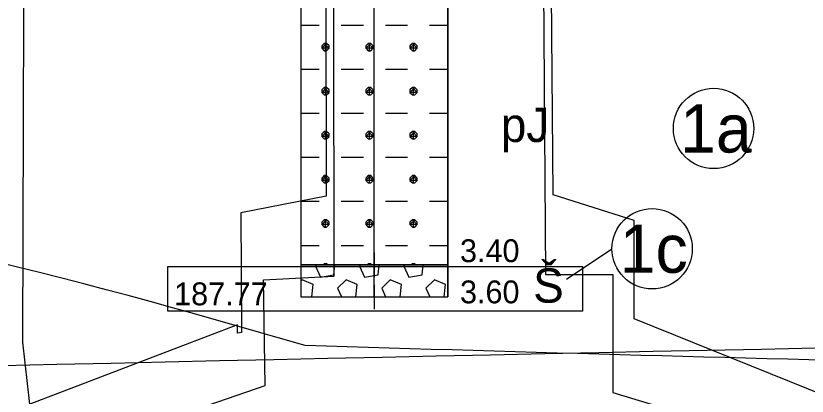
# Model space of a CAD drawing. Extents: x 3042 to 4120, y 576 to 2694.
# Drawn here: x 3366.29 to 3390.9, y 1724.37 to 1736.2 of the extents above; entities that cross this region are included whole.
import ezdxf

# ---------------------------------------------------------------- set-up
doc = ezdxf.new("R2010")
doc.units = 0
for name, color, linetype in [('17', 7, 'Continuous'), ('18', 7, 'Continuous'), ('51', 7, 'Continuous'), ('52', 7, 'Continuous'), ('53', 7, 'Continuous'), ('56', 7, 'Continuous'), ('HPV', 7, 'Continuous'), ('nádrže', 7, 'Continuous'), ('rozhraní', 7, 'Continuous')]:
    doc.layers.add(name, color=color, linetype=linetype)

msp = doc.modelspace()

# ---------------------------------------------------------------- linework, layer by layer
at = {"layer": '18'}
for p, q in [((3377.432, 1727.455), (3377.432, 1745.455)), ((3377.432, 1727.836), (3377.432, 1727.074)), ((3377.051, 1727.455), (3377.813, 1727.455))]:
    msp.add_line(p, q, dxfattribs=at)
at = {"layer": '51'}
for p, q in [((3375.146, 1735.917), (3375.722, 1735.917)), ((3376.408, 1735.917), (3377.094, 1735.917)), ((3377.779, 1735.917), (3378.465, 1735.917)), ((3379.151, 1735.917), (3379.718, 1735.917)), ((3375.912, 1735.117), (3375.912, 1735.346)), ((3377.284, 1735.117), (3377.284, 1735.346)), ((3378.656, 1735.117), (3378.656, 1735.346)), ((3375.146, 1734.546), (3375.722, 1734.546)), ((3376.408, 1734.546), (3377.094, 1734.546)), ((3377.779, 1734.546), (3378.465, 1734.546)), ((3379.151, 1734.546), (3379.718, 1734.546)), ((3375.912, 1733.746), (3375.912, 1733.974)), ((3377.284, 1733.746), (3377.284, 1733.974)), ((3378.656, 1733.746), (3378.656, 1733.974)), ((3375.146, 1733.174), (3375.722, 1733.174)), ((3376.408, 1733.174), (3377.094, 1733.174)), ((3377.779, 1733.174), (3378.465, 1733.174)), ((3379.151, 1733.174), (3379.718, 1733.174)), ((3375.912, 1732.374), (3375.912, 1732.603)), ((3377.284, 1732.374), (3377.284, 1732.603)), ((3378.656, 1732.374), (3378.656, 1732.603)), ((3375.146, 1731.803), (3375.722, 1731.803)), ((3376.408, 1731.803), (3377.094, 1731.803)), ((3377.779, 1731.803), (3378.465, 1731.803)), ((3379.151, 1731.803), (3379.718, 1731.803)), ((3375.912, 1731.003), (3375.912, 1731.231)), ((3377.284, 1731.003), (3377.284, 1731.231)), ((3378.656, 1731.003), (3378.656, 1731.231)), ((3375.146, 1730.431), (3375.722, 1730.431)), ((3376.408, 1730.431), (3377.094, 1730.431)), ((3377.779, 1730.431), (3378.465, 1730.431)), ((3379.151, 1730.431), (3379.718, 1730.431)), ((3375.912, 1729.631), (3375.912, 1729.86)), ((3377.284, 1729.631), (3377.284, 1729.86)), ((3378.656, 1729.631), (3378.656, 1729.86)), ((3375.146, 1729.059), (3375.722, 1729.059)), ((3376.408, 1729.059), (3377.094, 1729.059)), ((3377.779, 1729.059), (3378.465, 1729.059)), ((3379.151, 1729.059), (3379.718, 1729.059)), ((3375.651, 1728.455), (3375.608, 1728.412)), ((3375.874, 1728.488), (3375.841, 1728.455)), ((3375.912, 1728.455), (3375.912, 1728.488)), ((3375.917, 1728.455), (3375.951, 1728.488)), ((3377.022, 1728.455), (3376.979, 1728.412)), ((3377.246, 1728.488), (3377.213, 1728.455)), ((3377.284, 1728.455), (3377.284, 1728.488)), ((3377.289, 1728.455), (3377.322, 1728.488)), ((3378.394, 1728.455), (3378.351, 1728.412)), ((3378.618, 1728.488), (3378.584, 1728.455)), ((3378.656, 1728.455), (3378.656, 1728.488)), ((3378.66, 1728.455), (3378.694, 1728.488)), ((3376.293, 1727.726), (3376.414, 1727.455)), ((3377.665, 1727.726), (3377.786, 1727.455)), ((3379.037, 1727.726), (3379.157, 1727.455))]:
    msp.add_line(p, q, dxfattribs=at)
for points in [[(3375.146, 1728.455), (3379.718, 1728.455), (3379.718, 1737.455), (3375.146, 1737.455)], [(3375.146, 1727.455), (3379.718, 1727.455), (3379.718, 1728.455), (3375.146, 1728.455)]]:
    msp.add_lwpolyline(points, close=True, dxfattribs=at)
for points in [[(3375.874, 1735.346), (3375.798, 1735.27), (3375.798, 1735.194), (3375.874, 1735.117), (3375.951, 1735.117), (3376.027, 1735.194), (3376.027, 1735.27), (3375.951, 1735.346), (3375.874, 1735.346), (3376.027, 1735.194), (3375.798, 1735.194), (3375.951, 1735.346)], [(3377.246, 1735.346), (3377.17, 1735.27), (3377.17, 1735.194), (3377.246, 1735.117), (3377.322, 1735.117), (3377.398, 1735.194), (3377.398, 1735.27), (3377.322, 1735.346), (3377.246, 1735.346), (3377.398, 1735.194), (3377.17, 1735.194), (3377.322, 1735.346)], [(3378.618, 1735.346), (3378.541, 1735.27), (3378.541, 1735.194), (3378.618, 1735.117), (3378.694, 1735.117), (3378.77, 1735.194), (3378.77, 1735.27), (3378.694, 1735.346), (3378.618, 1735.346), (3378.77, 1735.194), (3378.541, 1735.194), (3378.694, 1735.346)], [(3375.874, 1733.974), (3375.798, 1733.898), (3375.798, 1733.822), (3375.874, 1733.746), (3375.951, 1733.746), (3376.027, 1733.822), (3376.027, 1733.898), (3375.951, 1733.974), (3375.874, 1733.974), (3376.027, 1733.822), (3375.798, 1733.822), (3375.951, 1733.974)], [(3377.246, 1733.974), (3377.17, 1733.898), (3377.17, 1733.822), (3377.246, 1733.746), (3377.322, 1733.746), (3377.398, 1733.822), (3377.398, 1733.898), (3377.322, 1733.974), (3377.246, 1733.974), (3377.398, 1733.822), (3377.17, 1733.822), (3377.322, 1733.974)], [(3378.618, 1733.974), (3378.541, 1733.898), (3378.541, 1733.822), (3378.618, 1733.746), (3378.694, 1733.746), (3378.77, 1733.822), (3378.77, 1733.898), (3378.694, 1733.974), (3378.618, 1733.974), (3378.77, 1733.822), (3378.541, 1733.822), (3378.694, 1733.974)], [(3375.874, 1732.603), (3375.798, 1732.527), (3375.798, 1732.45), (3375.874, 1732.374), (3375.951, 1732.374), (3376.027, 1732.45), (3376.027, 1732.527), (3375.951, 1732.603), (3375.874, 1732.603), (3376.027, 1732.45), (3375.798, 1732.45), (3375.951, 1732.603)], [(3377.246, 1732.603), (3377.17, 1732.527), (3377.17, 1732.45), (3377.246, 1732.374), (3377.322, 1732.374), (3377.398, 1732.45), (3377.398, 1732.527), (3377.322, 1732.603), (3377.246, 1732.603), (3377.398, 1732.45), (3377.17, 1732.45), (3377.322, 1732.603)], [(3378.618, 1732.603), (3378.541, 1732.527), (3378.541, 1732.45), (3378.618, 1732.374), (3378.694, 1732.374), (3378.77, 1732.45), (3378.77, 1732.527), (3378.694, 1732.603), (3378.618, 1732.603), (3378.77, 1732.45), (3378.541, 1732.45), (3378.694, 1732.603)], [(3375.874, 1731.231), (3375.798, 1731.155), (3375.798, 1731.079), (3375.874, 1731.003), (3375.951, 1731.003), (3376.027, 1731.079), (3376.027, 1731.155), (3375.951, 1731.231), (3375.874, 1731.231), (3376.027, 1731.079), (3375.798, 1731.079), (3375.951, 1731.231)], [(3377.246, 1731.231), (3377.17, 1731.155), (3377.17, 1731.079), (3377.246, 1731.003), (3377.322, 1731.003), (3377.398, 1731.079), (3377.398, 1731.155), (3377.322, 1731.231), (3377.246, 1731.231), (3377.398, 1731.079), (3377.17, 1731.079), (3377.322, 1731.231)], [(3378.618, 1731.231), (3378.541, 1731.155), (3378.541, 1731.079), (3378.618, 1731.003), (3378.694, 1731.003), (3378.77, 1731.079), (3378.77, 1731.155), (3378.694, 1731.231), (3378.618, 1731.231), (3378.77, 1731.079), (3378.541, 1731.079), (3378.694, 1731.231)], [(3375.874, 1729.86), (3375.798, 1729.783), (3375.798, 1729.707), (3375.874, 1729.631), (3375.951, 1729.631), (3376.027, 1729.707), (3376.027, 1729.783), (3375.951, 1729.86), (3375.874, 1729.86), (3376.027, 1729.707), (3375.798, 1729.707), (3375.951, 1729.86)], [(3377.246, 1729.86), (3377.17, 1729.783), (3377.17, 1729.707), (3377.246, 1729.631), (3377.322, 1729.631), (3377.398, 1729.707), (3377.398, 1729.783), (3377.322, 1729.86), (3377.246, 1729.86), (3377.398, 1729.707), (3377.17, 1729.707), (3377.322, 1729.86)], [(3378.618, 1729.86), (3378.541, 1729.783), (3378.541, 1729.707), (3378.618, 1729.631), (3378.694, 1729.631), (3378.77, 1729.707), (3378.77, 1729.783), (3378.694, 1729.86), (3378.618, 1729.86), (3378.77, 1729.707), (3378.541, 1729.707), (3378.694, 1729.86)], [(3375.608, 1728.412), (3375.76, 1728.069), (3376.179, 1728.145), (3376.21, 1728.455)], [(3375.984, 1728.455), (3375.951, 1728.488), (3375.874, 1728.488), (3375.908, 1728.455)], [(3376.979, 1728.412), (3377.132, 1728.069), (3377.551, 1728.145), (3377.582, 1728.455)], [(3377.355, 1728.455), (3377.322, 1728.488), (3377.246, 1728.488), (3377.279, 1728.455)], [(3378.351, 1728.412), (3378.503, 1728.069), (3378.922, 1728.145), (3378.953, 1728.455)], [(3378.727, 1728.455), (3378.694, 1728.488), (3378.618, 1728.488), (3378.651, 1728.455)], [(3379.722, 1728.412), (3379.722, 1728.412), (3379.722, 1728.412)], [(3375.468, 1727.455), (3375.493, 1727.459), (3375.531, 1727.84), (3375.189, 1727.993), (3375.146, 1727.95)], [(3376.84, 1727.455), (3376.865, 1727.459), (3376.903, 1727.84), (3376.56, 1727.993), (3376.293, 1727.726)], [(3378.212, 1727.455), (3378.237, 1727.459), (3378.275, 1727.84), (3377.932, 1727.993), (3377.665, 1727.726)], [(3379.583, 1727.455), (3379.608, 1727.459), (3379.646, 1727.84), (3379.303, 1727.993), (3379.037, 1727.726)]]:
    msp.add_lwpolyline(points, dxfattribs=at)
at = {"layer": '53'}
for p, q in [((3375.146, 1745.455), (3375.146, 1727.455)), ((3379.718, 1745.455), (3379.718, 1727.455)), ((3375.146, 1728.455), (3379.718, 1728.455)), ((3375.146, 1727.455), (3379.718, 1727.455))]:
    msp.add_line(p, q, dxfattribs=at)
at = {"layer": '56'}
for p, q in [((3377.432, 1728.836), (3377.432, 1728.074)), ((3377.051, 1728.455), (3377.813, 1728.455)), ((3377.432, 1727.836), (3377.432, 1727.074)), ((3377.051, 1727.455), (3377.813, 1727.455))]:
    msp.add_line(p, q, dxfattribs=at)
at = {"layer": 'HPV'}
msp.add_spline([(3230.252, 1725.131), (3237.162, 1725.131), (3320.372, 1724.616), (3428.242, 1726.321), (3436.076, 1726.321)], degree=3, dxfattribs=at)
at = {"layer": 'nádrže'}
for points in [[(3367.787, 1722.543), (3374.038, 1724.7), (3373.993, 1727.984), (3376.184, 1728.097), (3376.166, 1744.369), (3375.766, 1744.358), (3375.767, 1743.136), (3375.921, 1743.14), (3375.935, 1730.588), (3373.279, 1730.071), (3373.308, 1726.354), (3373.177, 1726.328), (3373.175, 1726.585), (3366.724, 1724.121), (3366.506, 1726.05), (3366.551, 1743.148), (3366.821, 1743.149), (3366.817, 1744.162), (3364.973, 1744.162)], [(3392.173, 1724.093), (3385.521, 1726.779), (3385.511, 1729.837), (3383, 1730.628), (3382.898, 1743.192), (3383.022, 1743.217), (3383.016, 1744.273), (3382.597, 1744.273), (3382.587, 1743.068), (3382.652, 1743.054)], [(3382.652, 1743.054), (3382.757, 1728.152), (3384.857, 1728.152), (3384.857, 1724.48), (3390.553, 1722.753)]]:
    msp.add_lwpolyline(points, dxfattribs=at)
at = {"layer": 'rozhraní'}
msp.add_lwpolyline([(3383.407, 1728.011), (3384.824, 1728.956), (3384.824, 1728.956)], dxfattribs=at)
msp.add_lwpolyline([(3371.016, 1728.4), (3383.907, 1728.4), (3383.907, 1727.01), (3371.016, 1727.01)], close=True, dxfattribs=at)
for centre in [(3387.986, 1732.699), (3386.074, 1728.956)]:
    msp.add_circle(centre, 1.25, dxfattribs=at)
for points in [[(3375.28, 1725.942), (3353.275, 1730.254), (3328.265, 1725.266)], [(3436.623, 1725.567), (3417.072, 1725.205), (3375.28, 1725.942)]]:
    msp.add_spline(points, degree=3, dxfattribs=at)

# ---------------------------------------------------------------- texts
at = {"layer": '17'}
msp.add_text('187.77', height=0.7112, dxfattribs=at).set_placement((3371.209, 1727.196))
at = {"layer": '52'}
for s, height, p in [('pJ', 1.0668, (3381.369, 1732.277)), ('3.40', 0.7112, (3380.099, 1728.538)), ('Š', 1.067, (3382.375, 1727.277)), ('3.60', 0.7112, (3380.099, 1727.257))]:
    msp.add_text(s, height=height, dxfattribs=at).set_placement(p)
at = {"layer": 'rozhraní'}
for s, p in [('1a', (3386.942, 1731.949)), ('1c', (3385.064, 1728.206))]:
    msp.add_text(s, height=1.5, dxfattribs=at).set_placement(p)

doc.saveas('drawing.dxf')
